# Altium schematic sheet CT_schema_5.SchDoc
size 255 x 245 mm
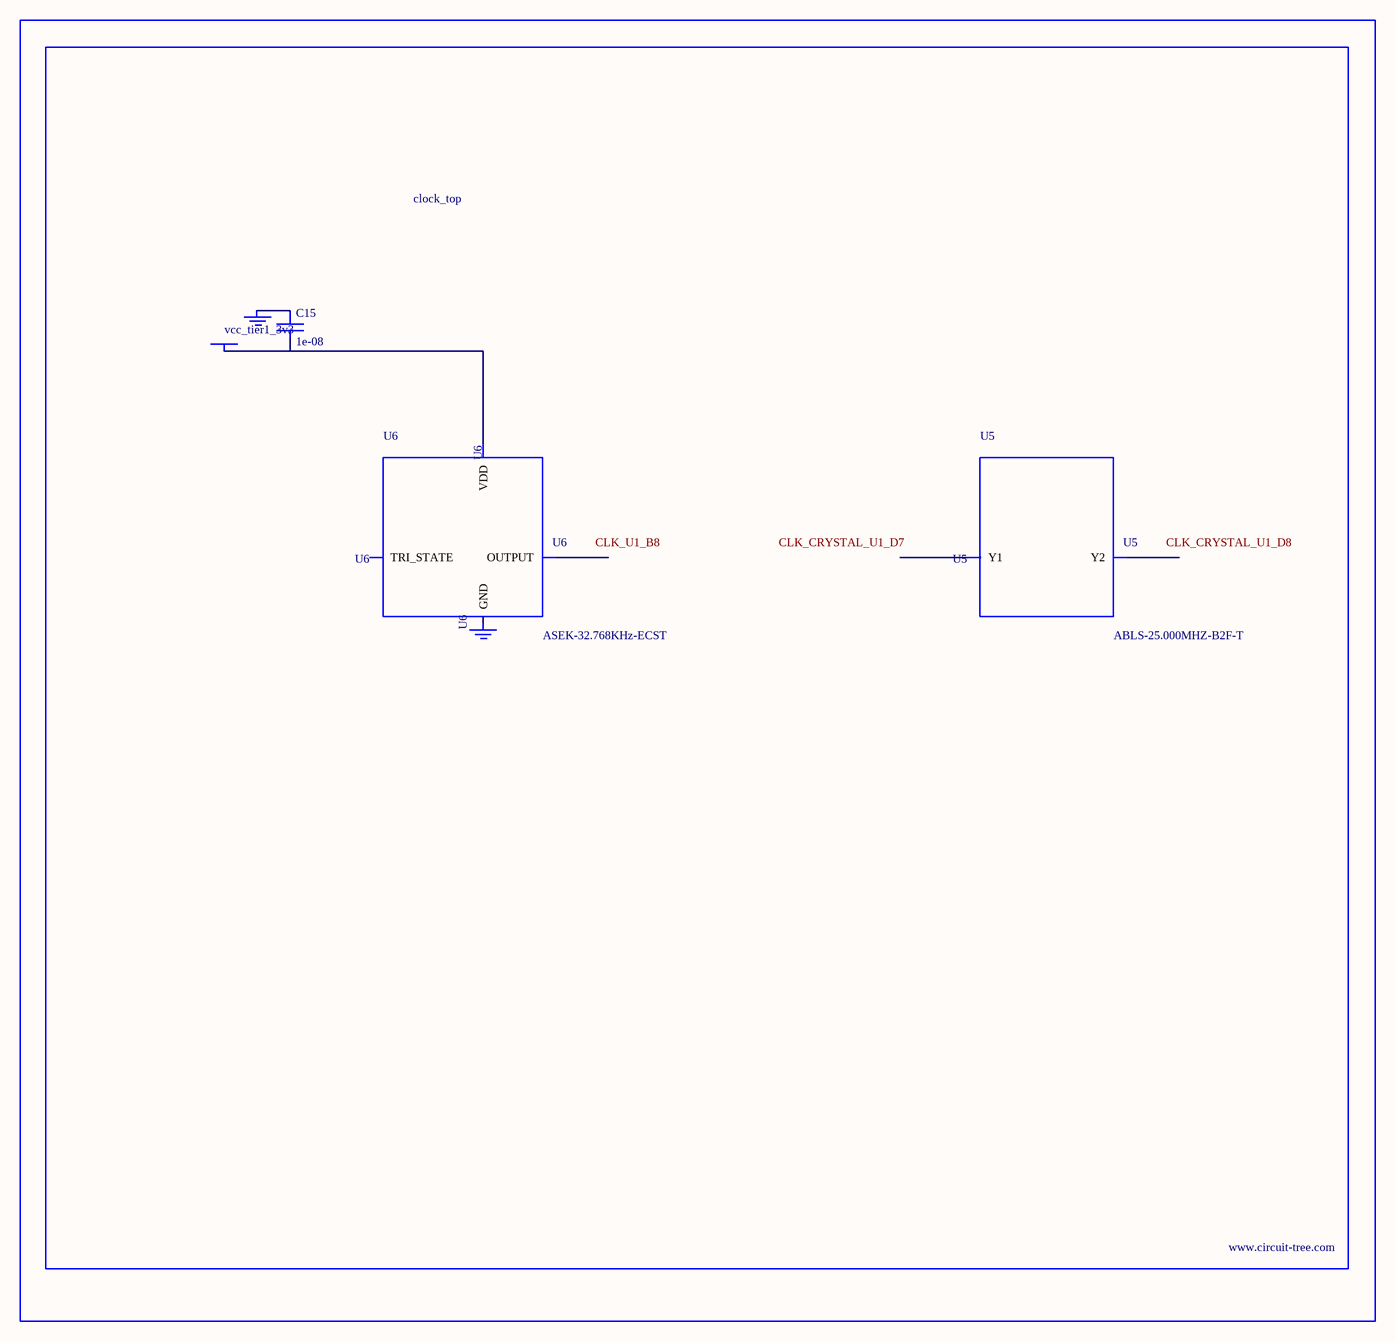
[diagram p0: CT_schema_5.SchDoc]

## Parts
BORDER4  (no value)
C15  1e-08  [C0402]
GND_INSTANCE_4_0  (no value)
GND_INSTANCE_4_1  (no value)
POWER_INSTANCE_4_0  vcc_tier1_3v3
U5  ABLS-25.000MHZ-B2F-T  [ABLS-25.000MHZ-B2F-T]
U6  ASEK-32.768KHz-ECST  [ASEK]

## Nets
NetC15_1: C15.1 GND_INSTANCE_4_0.0(GND)
NetC15_2: C15.2 POWER_INSTANCE_4_0.0(PWR) U6.4(VDD)

Not connected (* = marked no-connect by the designer): GND_INSTANCE_4_1 0(GND); U5 1(Y1) 2(Y2); U6 1(TRI_STATE) 2(GND) 3(OUTPUT)

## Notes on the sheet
- Labels drawn without touching a wire or pin: CLK_CRYSTAL_U1_D7, CLK_CRYSTAL_U1_D8, CLK_U1_B8

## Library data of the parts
BORDER4 = BORDER_PAGE4
C15 = C0402C103K3RAC
GND_INSTANCE_4_0 GND_INSTANCE_4_1 = GND
POWER_INSTANCE_4_0 = PWR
